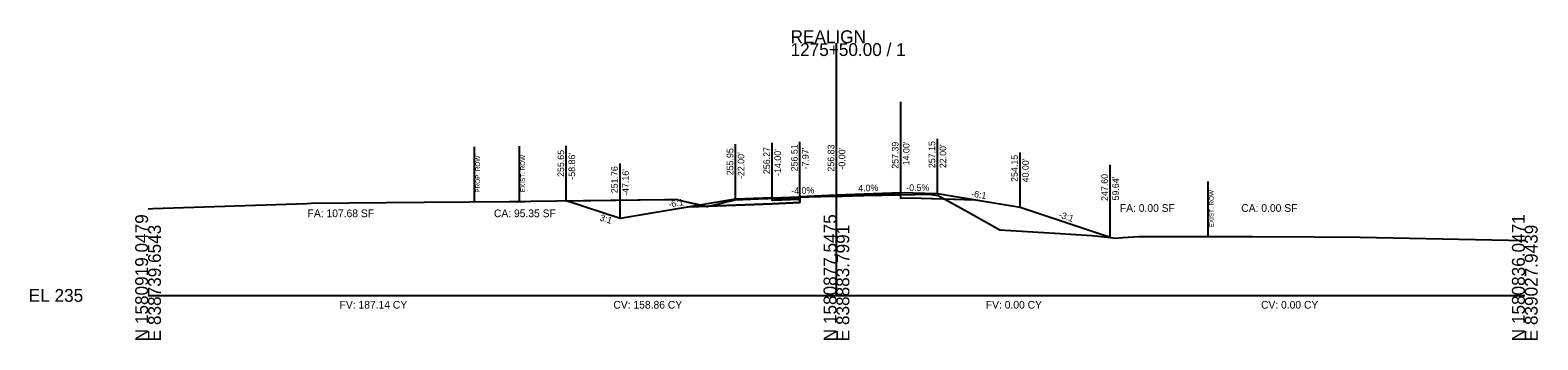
# Model space of a CAD drawing. Extents: x -26 to 6303, y -16 to 9563.
# Drawn here: x 4974.3 to 5302.8, y 8990.3 to 9057.8 of the extents above; entities that cross this region are included whole.
import ezdxf

# ---------------------------------------------------------------- set-up
doc = ezdxf.new("R2010")
doc.units = 0
for name, color, linetype in [('ASPHALT_19MM1', 7, 'Continuous'), ('ASPHALT_9_5MM1', 7, 'Continuous'), ('Default', 7, 'Continuous'), ('Draft_XS_Grid', 7, 'Continuous'), ('DTM_TEMP_DROP', 7, 'Continuous'), ('DTM_X_GROUND', 7, 'Continuous'), ('X_TRANS_EOP', 7, 'Continuous'), ('XS_CELL', 7, 'Continuous'), ('XS_M_SHAPES_EARTHWORK', 7, 'Continuous'), ('XS_P_ASPHALT', 7, 'Continuous'), ('XS_P_GROUND', 7, 'Continuous'), ('XS_P_ROW', 7, 'Continuous'), ('XS_P_SHOULDER', 7, 'Continuous'), ('XS_P_SUBGRADE_GRANULAR', 7, 'Continuous'), ('XS_P_SUBGRADE_LEVELING', 7, 'Continuous'), ('XS_P_SUBGRADE_MILLING', 7, 'Continuous'), ('XS_P_TX_CLEARZONE', 7, 'Continuous'), ('XS_P_TX_FS_BS', 7, 'Continuous'), ('XS_SHEET_EW_TX_AREA', 7, 'Continuous'), ('XS_SHEET_EW_TX_VOLUME', 7, 'Continuous'), ('XS_X_ROW', 7, 'Continuous')]:
    doc.layers.add(name, color=color, linetype=linetype)

msp = doc.modelspace()

# ---------------------------------------------------------------- linework, layer by layer
at = {"layer": 'ASPHALT_19MM1'}
msp.add_lwpolyline([(5142.03, 9021.18), (5142.03, 9020.91), (5136, 9020.67), (5136, 9020.94), (5142.03, 9021.18)], dxfattribs=at)
at = {"layer": 'ASPHALT_9_5MM1'}
msp.add_lwpolyline([(5142.03, 9021.51), (5142.03, 9021.39), (5136, 9021.14), (5136, 9021.27), (5142.03, 9021.51)], dxfattribs=at)
at = {"layer": 'Default'}
msp.add_lwpolyline([(5142.03, 9021.39), (5142.03, 9021.18), (5136, 9020.94), (5136, 9021.14), (5142.03, 9021.39)], dxfattribs=at)
at = {"layer": 'DTM_X_GROUND'}
msp.add_lwpolyline([(5000, 9018.86), (5001.07, 9018.92), (5034.63, 9020.06), (5035.52, 9020.09), (5060.14, 9020.33), (5070.03, 9020.4), (5078.67, 9020.49), (5082.14, 9020.51), (5083.4, 9020.54), (5088.99, 9020.63), (5112.61, 9020.92), (5113.84, 9020.94), (5114.36, 9020.94), (5115.09, 9020.95), (5115.73, 9020.75), (5121.9, 9019.37), (5123.98, 9019.91), (5127.9, 9020.85), (5133.04, 9021.03), (5137.27, 9021.19), (5140.95, 9021.4), (5142.03, 9021.46), (5151.23, 9021.66), (5155.99, 9021.76), (5167.06, 9022), (5169.9, 9022.06), (5170.01, 9022.05), (5172.18, 9021.77), (5178.61, 9018.21), (5185.64, 9014.32), (5197.62, 9013.56), (5205.67, 9013.05), (5209.05, 9012.67), (5210.7, 9012.48), (5212.42, 9012.61), (5215.87, 9012.88), (5224.79, 9012.87), (5235.79, 9012.84), (5240.64, 9012.83), (5254.15, 9012.76), (5264.14, 9012.7), (5300, 9011.98)], dxfattribs=at)
at = {"layer": 'X_TRANS_EOP'}
msp.add_line((5164, 9022.19), (5164, 9042.19), dxfattribs=at)
at = {"layer": 'XS_CELL'}
for p, q in [((5150, 9000), (5150, 9055)), ((5000, 9000), (5150, 9000)), ((5150, 9000), (5300, 9000))]:
    msp.add_line(p, q, dxfattribs=at)
at = {"layer": 'XS_M_SHAPES_EARTHWORK'}
for points in [[(5122.2, 9019.45), (5123.98, 9019.91), (5127.9, 9020.85), (5133.04, 9021.03), (5137.27, 9021.19), (5140.95, 9021.4), (5142.03, 9021.46), (5145.91, 9021.54), (5142.03, 9021.39), (5142.03, 9021.18), (5142.03, 9020.91), (5142.03, 9020.24), (5136, 9020), (5134, 9019.92)], [(5164, 9021.93), (5167.06, 9022), (5169.9, 9022.06), (5170.01, 9022.05), (5172.18, 9021.77), (5173.63, 9020.97), (5166, 9021.2), (5164, 9021.12)], [(5091.14, 9020.65), (5112.61, 9020.92), (5113.84, 9020.94), (5114.36, 9020.94), (5115.09, 9020.95), (5115.73, 9020.75), (5121.65, 9019.42), (5117.97, 9019.28), (5102.84, 9016.76)], [(5121.65, 9019.42), (5121.9, 9019.37), (5122.2, 9019.45)], [(5173.63, 9020.97), (5178.61, 9018.21), (5185.64, 9014.32), (5197.62, 9013.56), (5205.67, 9013.05), (5209.05, 9012.67), (5209.64, 9012.6), (5190, 9019.15), (5180.27, 9020.77)]]:
    msp.add_lwpolyline(points, close=True, dxfattribs=at)
at = {"layer": 'XS_P_ASPHALT'}
msp.add_lwpolyline([(5142.03, 9021.39), (5142.03, 9021.39), (5150, 9021.7), (5150, 9021.7), (5164, 9022.26), (5164, 9022.39), (5150, 9021.83), (5150, 9021.83), (5142.03, 9021.51), (5142.03, 9021.51), (5142.03, 9021.39)], dxfattribs=at)
at = {"layer": 'XS_P_GROUND'}
for points in [[(5209.64, 9012.6), (5209.64, 9012.6), (5190, 9019.15), (5190, 9019.15), (5172, 9022.15)], [(5128, 9020.95), (5102.84, 9016.76), (5091.14, 9020.65)]]:
    msp.add_lwpolyline(points, dxfattribs=at)
at = {"layer": 'XS_P_ROW'}
msp.add_line((5071.12, 9020.41), (5071.12, 9032.41), dxfattribs=at)
at = {"layer": 'XS_P_SHOULDER'}
for points in [[(5172, 9022.15), (5172, 9022.15), (5164, 9022.39)], [(5136, 9021.27), (5128, 9020.95)]]:
    msp.add_lwpolyline(points, dxfattribs=at)
at = {"layer": 'XS_P_SUBGRADE_GRANULAR'}
for points in [[(5142.03, 9020.24), (5142.03, 9021.51)], [(5164, 9021.12), (5164, 9022.39)], [(5117.97, 9019.28), (5117.97, 9019.28), (5134, 9019.92), (5134, 9019.92), (5136, 9020)], [(5136, 9020), (5136, 9020), (5142.03, 9020.24)], [(5180.27, 9020.77), (5180.27, 9020.77), (5166, 9021.2), (5164, 9021.12), (5164, 9021.12)]]:
    msp.add_lwpolyline(points, dxfattribs=at)
at = {"layer": 'XS_P_SUBGRADE_LEVELING'}
msp.add_lwpolyline([(5142.03, 9021.39), (5142.03, 9021.39), (5145.91, 9021.54), (5150, 9021.63), (5150, 9021.63), (5151.23, 9021.66), (5151.23, 9021.66), (5155.99, 9021.76), (5155.99, 9021.76), (5164, 9021.93), (5164, 9021.93), (5164, 9022.26), (5155.99, 9021.94), (5155.99, 9021.94), (5151.23, 9021.75), (5151.23, 9021.75), (5150, 9021.7), (5142.03, 9021.39), (5142.03, 9021.39)], dxfattribs=at)
at = {"layer": 'XS_P_SUBGRADE_MILLING'}
msp.add_lwpolyline([(5164, 9021.93), (5155.99, 9021.76), (5155.99, 9021.76), (5151.23, 9021.66), (5151.23, 9021.66), (5150, 9021.63), (5142.03, 9021.46), (5142.03, 9021.46), (5142.03, 9021.39), (5142.03, 9021.39), (5145.91, 9021.54), (5150, 9021.63), (5150, 9021.63), (5151.23, 9021.66), (5151.23, 9021.66), (5155.99, 9021.76), (5155.99, 9021.76), (5164, 9021.93)], dxfattribs=at)
at = {"layer": 'XS_P_TX_CLEARZONE'}
for p, q in [((5091.14, 9020.65), (5091.14, 9032.65)), ((5128, 9020.95), (5128, 9032.95)), ((5136, 9021.27), (5136, 9033.27)), ((5142.03, 9021.51), (5142.03, 9033.51)), ((5150, 9021.83), (5150, 9033.83)), ((5164, 9022.39), (5164, 9034.39)), ((5172, 9022.15), (5172, 9034.15)), ((5102.84, 9016.76), (5102.84, 9028.76)), ((5190, 9019.15), (5190, 9031.15)), ((5209.64, 9012.6), (5209.64, 9028.47))]:
    msp.add_line(p, q, dxfattribs=at)
at = {"layer": 'XS_X_ROW'}
for p, q in [((5080.94, 9020.51), (5080.94, 9032.51)), ((5231, 9012.85), (5231, 9024.85))]:
    msp.add_line(p, q, dxfattribs=at)

# ---------------------------------------------------------------- texts
at = {"layer": 'Draft_XS_Grid'}
msp.add_text('-', height=0.0001, dxfattribs=at).set_placement((5000, 9000))
at = {"layer": 'DTM_TEMP_DROP'}
for p in [(5141.95, 9021.39), (5149.92, 9021.71), (5163.92, 9022.27), (5135.92, 9021.15)]:
    msp.add_text('X', height=0.24, dxfattribs=at).set_placement(p)
at = {"layer": 'X_TRANS_EOP'}
for p in [(5091.06, 9020.53), (5209.56, 9012.48)]:
    msp.add_text('X', height=0.24, dxfattribs=at).set_placement(p)
at = {"layer": 'XS_CELL'}
for s, p in [('REALIGN', (5140, 9055)), ('1275+50.00 / 1', (5140, 9052.2)), ('EL 235', (4974, 8998.6))]:
    msp.add_text(s, height=2.8, dxfattribs=at).set_placement(p)
for s, p in [('N 1580919.0479', (5000, 8990)), ('E 838739.6543', (5002.8, 8990)), ('N 1580877.5475', (5150, 8990)), ('E 838883.7991', (5152.8, 8990)), ('N 1580836.0471', (5300, 8990)), ('E 839027.9439', (5302.8, 8990))]:
    msp.add_text(s, height=2.8, rotation=90, dxfattribs=at).set_placement(p)
at = {"layer": 'XS_P_ASPHALT'}
msp.add_text('X', height=0.24, dxfattribs=at).set_placement((5189.92, 9019.03))
at = {"layer": 'XS_P_ROW'}
msp.add_text('PROP. ROW', height=1, rotation=90, dxfattribs=at).set_placement((5072.33, 9022.41))
at = {"layer": 'XS_P_SHOULDER'}
for p in [(5171.92, 9022.03), (5127.92, 9020.83)]:
    msp.add_text('X', height=0.24, dxfattribs=at).set_placement(p)
at = {"layer": 'XS_P_SUBGRADE_GRANULAR'}
for p in [(5102.76, 9016.64), (5209.56, 9012.48)]:
    msp.add_text('X', height=0.24, dxfattribs=at).set_placement(p)
at = {"layer": 'XS_P_TX_CLEARZONE'}
for s, p in [('255.65', (5090.66, 9025.83)), ('255.95', (5127.52, 9026.2)), ('256.27', (5135.52, 9026.45)), ("-14.00'", (5137.92, 9026.06)), ('256.51', (5141.55, 9027.05)), ("-7.97'", (5143.95, 9027.46)), ('256.83', (5149.52, 9027.01)), ("-0.00'", (5151.92, 9027.44)), ('257.39', (5163.52, 9027.62)), ("14.00'", (5165.92, 9028.36)), ('257.15', (5171.52, 9027.76)), ("22.00'", (5173.92, 9027.76)), ("-58.86'", (5093.06, 9025.24)), ('251.76', (5102.36, 9022.28)), ("-22.00'", (5129.92, 9025.38)), ('254.15', (5189.52, 9024.76)), ("40.00'", (5191.92, 9024.64)), ("-47.16'", (5104.76, 9021.71)), ('247.60', (5209.16, 9020.59)), ("59.64'", (5211.56, 9020.7))]:
    msp.add_text(s, height=1.44, rotation=90, dxfattribs=at).set_placement(p)
at = {"layer": 'XS_P_TX_FS_BS'}
for s, rotation, p in [('-4.0%', 2.2906, (5140.18, 9022.04)), ('4.0%', 2.2906, (5154.77, 9022.62)), ('-0.5%', 359.7214, (5165.21, 9022.78)), ('-6:1', 350.5377, (5179.28, 9021.55)), ('-6:1', 9.4642, (5113.5, 9019.14)), ('3:1', 341.5668, (5098.29, 9016.39)), ('-3:1', 341.5651, (5198.29, 9017.02))]:
    msp.add_text(s, height=1.44, rotation=rotation, dxfattribs=at).set_placement(p)
at = {"layer": 'XS_SHEET_EW_TX_AREA'}
for s, p in [('FA: 107.68 SF', (5034.76, 9017.06)), ('CA: 95.35 SF', (5075.37, 9017.06)), ('FA: 0.00 SF', (5211.76, 9018.22)), ('CA: 0.00 SF', (5238.21, 9018.22))]:
    msp.add_text(s, height=1.68, dxfattribs=at).set_placement(p)
at = {"layer": 'XS_SHEET_EW_TX_VOLUME'}
for s, p in [('FV: 187.14 CY', (5041.73, 8997.12)), ('CV: 158.86 CY', (5101.4, 8997.12)), ('FV: 0.00 CY', (5182.55, 8997.12)), ('CV: 0.00 CY', (5242.51, 8997.12))]:
    msp.add_text(s, height=1.68, dxfattribs=at).set_placement(p)
at = {"layer": 'XS_X_ROW'}
for p in [(5082.14, 9022.51), (5232.2, 9014.85)]:
    msp.add_text('EXIST. ROW', height=1, rotation=90, dxfattribs=at).set_placement(p)

doc.saveas('drawing.dxf')
